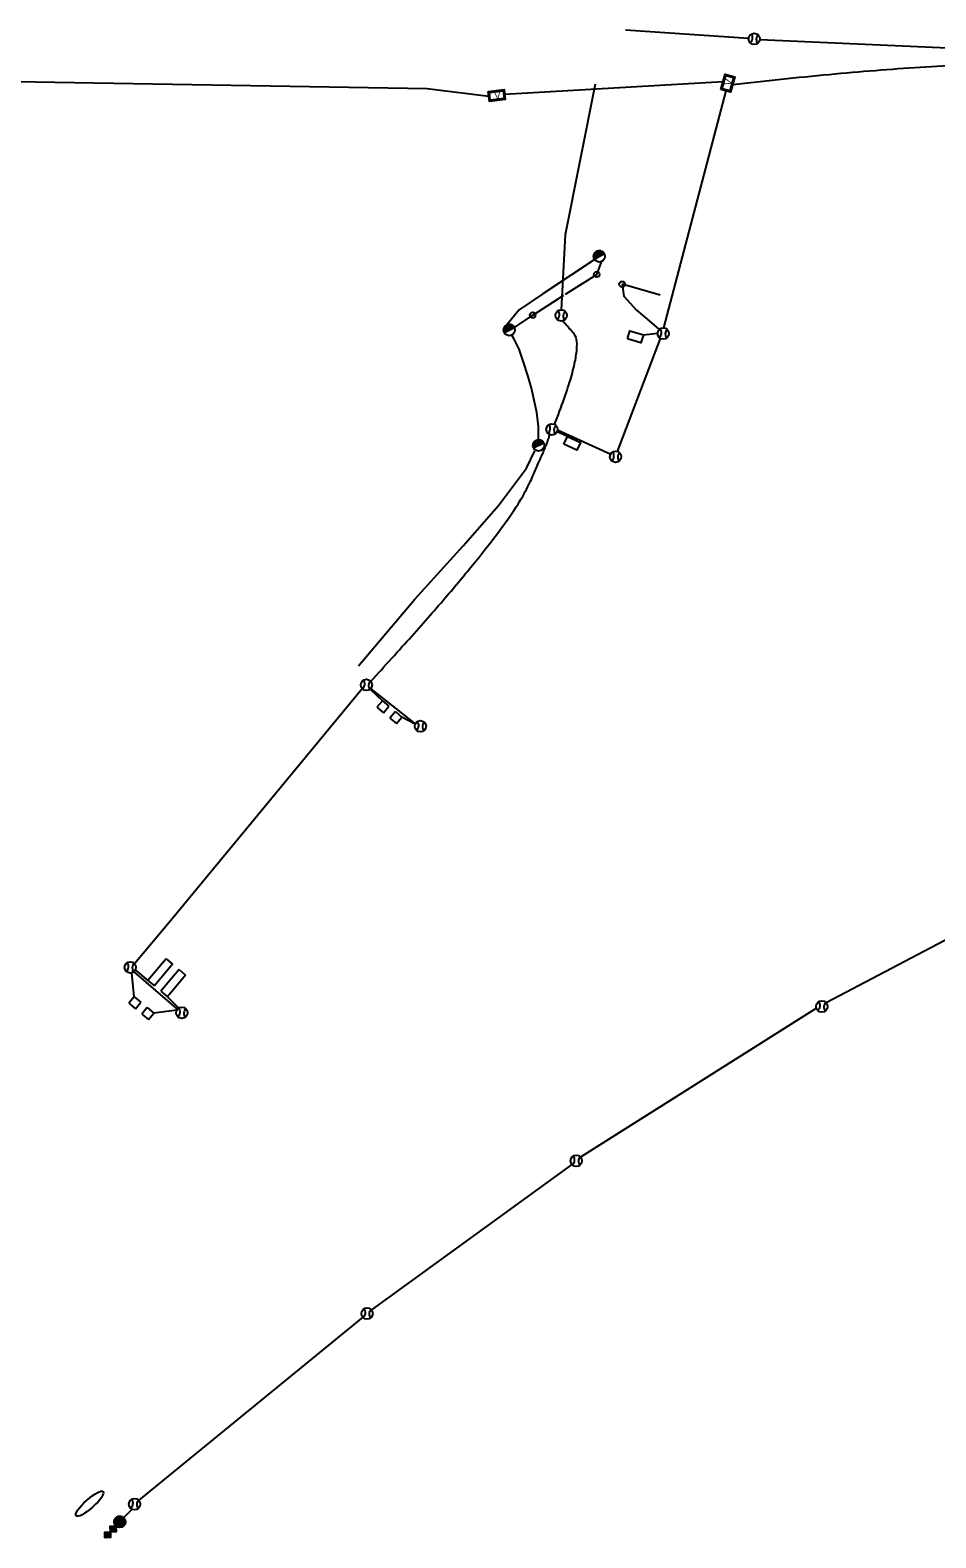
# Model space of a CAD drawing. Extents: x 0 to 2149228, y 0 to 2148913.
# Drawn here: x 595979 to 596619, y 230134 to 231199 of the extents above; entities that cross this region are included whole.
import ezdxf

# ---------------------------------------------------------------- set-up
doc = ezdxf.new("R2010")
doc.units = 0
for name, color, linetype in [('Default', 7, 'Continuous'), ('P_FTMS_2013 _CONDUIT', 7, 'Continuous'), ('P_FTMS_2013_NOT_CONDUIT', 7, 'Continuous'), ('P_TC_Drums_100_50', 7, 'Continuous')]:
    doc.layers.add(name, color=color, linetype=linetype)

# ---------------------------------------------------------------- blocks, each defined once
blk = doc.blocks.new('PB24X42')
at = {"layer": 'P_TC_Drums_100_50'}
blk.add_circle((0, 0), 2, dxfattribs=at)
for centre, start, end in [((-2.59, 0.09), 308.3742, 47.6044), ((2.73, 0.07), 134.4184, 228.4474)]:
    blk.add_arc(centre, 2, start, end, dxfattribs=at)

msp = doc.modelspace()

# ---------------------------------------------------------------- linework, layer by layer
at = {"layer": 'Default'}
for p, q in [((596378.3, 231041.9), (596377.2, 231038.6)), ((596377.8, 231041.3), (596377.2, 231039.3)), ((596378.6, 231042.2), (596377.3, 231038.1)), ((596381.1, 231039.1), (596377.3, 231040.4)), ((596379, 231042.5), (596377.4, 231037.7)), ((596381.4, 231039.3), (596377.4, 231040.6)), ((596379.3, 231042.6), (596377.5, 231037.4)), ((596381.8, 231039.4), (596377.5, 231040.8)), ((596382.1, 231039.6), (596377.6, 231041)), ((596377.6, 231037.3), (596384.7, 231040.9)), ((596379.6, 231042.8), (596377.8, 231037.4)), ((596382.4, 231039.7), (596377.8, 231041.2)), ((596382.7, 231039.9), (596377.9, 231041.5)), ((596379.9, 231042.9), (596378.1, 231037.6)), ((596383, 231040.1), (596378.1, 231041.7)), ((596383.3, 231040.2), (596378.2, 231041.9)), ((596380.1, 231043), (596378.4, 231037.7)), ((596383.6, 231040.4), (596378.4, 231042)), ((596383.9, 231040.5), (596378.6, 231042.2)), ((596380.4, 231043), (596378.7, 231037.9)), ((596384.2, 231040.7), (596378.9, 231042.4)), ((596380.7, 231043.1), (596379, 231038.1)), ((596384.5, 231040.8), (596379.1, 231042.6)), ((596380.9, 231043.1), (596379.3, 231038.2)), ((596384.7, 231041), (596379.4, 231042.7)), ((596381.2, 231043.1), (596379.6, 231038.4)), ((596384.5, 231041.3), (596379.8, 231042.9)), ((596381.4, 231043.1), (596379.9, 231038.5)), ((596384.2, 231041.7), (596380.1, 231043)), ((596381.7, 231043.1), (596380.2, 231038.7)), ((596381.9, 231043), (596380.5, 231038.8)), ((596383.9, 231042), (596380.6, 231043.1)), ((596382.2, 231043), (596380.8, 231039)), ((596382.4, 231042.9), (596381.1, 231039.1)), ((596383.4, 231042.4), (596381.3, 231043.1)), ((596382.6, 231042.8), (596381.4, 231039.3)), ((596382.8, 231042.8), (596381.8, 231039.4)), ((596383, 231042.6), (596382.1, 231039.6)), ((596383.3, 231042.5), (596382.4, 231039.7)), ((596383.5, 231042.4), (596382.7, 231039.9)), ((596383.7, 231042.2), (596383, 231040.1)), ((596383.9, 231042.1), (596383.3, 231040.2)), ((596384.1, 231041.9), (596383.6, 231040.4)), ((596384.2, 231041.7), (596383.9, 231040.5)), ((596384.4, 231041.4), (596384.2, 231040.7)), ((596384.6, 231041.2), (596384.5, 231040.8)), ((596384.7, 231041), (596384.7, 231040.9)), ((596380.5, 231038.8), (596377.2, 231039.9)), ((596380.2, 231038.7), (596377.2, 231039.7)), ((596379.9, 231038.5), (596377.2, 231039.4)), ((596379.6, 231038.4), (596377.2, 231039.2)), ((596379.3, 231038.2), (596377.2, 231038.9)), ((596379, 231038.1), (596377.2, 231038.7)), ((596378.7, 231037.9), (596377.2, 231038.4)), ((596380.8, 231039), (596377.3, 231040.1)), ((596378.4, 231037.7), (596377.3, 231038.1)), ((596378.1, 231037.6), (596377.4, 231037.8)), ((596377.8, 231037.4), (596377.5, 231037.6)), ((596377.6, 231037.3), (596377.6, 231037.3)), ((596377.6, 231037.3), (596377.6, 231037.3)), ((596379.3, 231026.4), (596383, 231035.6)), ((596357.4, 231012.4), (596379.3, 231026.4)), ((596424.1, 231011.6), (596397.2, 231019.4)), ((596334.1, 230997.6), (596356.1, 231011.6)), ((596316.1, 230986.3), (596313.6, 230987.2)), ((596314.7, 230989.9), (596313.7, 230986.6)), ((596314.3, 230989.3), (596313.7, 230987.3)), ((596317, 230986.8), (596313.7, 230987.9)), ((596316.7, 230986.7), (596313.7, 230987.6)), ((596316.4, 230986.5), (596313.7, 230987.4)), ((596315.1, 230990.2), (596313.8, 230986.1)), ((596317.6, 230987.1), (596313.8, 230988.4)), ((596317.3, 230987), (596313.8, 230988.1)), ((596315.4, 230990.5), (596313.9, 230985.7)), ((596317.9, 230987.3), (596313.9, 230988.6)), ((596315.7, 230990.6), (596314, 230985.4)), ((596318.2, 230987.4), (596314, 230988.8)), ((596318.5, 230987.6), (596314.1, 230989)), ((596314.1, 230985.3), (596321.2, 230988.9)), ((596316.1, 230990.8), (596314.3, 230985.4)), ((596318.8, 230987.7), (596314.3, 230989.2)), ((596319.1, 230987.9), (596314.4, 230989.4)), ((596319.4, 230988), (596314.5, 230989.6)), ((596316.3, 230990.9), (596314.6, 230985.6)), ((596319.8, 230988.2), (596314.7, 230989.8)), ((596316.6, 230991), (596314.9, 230985.7)), ((596320.1, 230988.3), (596314.9, 230990)), ((596320.4, 230988.5), (596315.1, 230990.2)), ((596316.9, 230991), (596315.2, 230985.9)), ((596320.7, 230988.7), (596315.3, 230990.4)), ((596317.2, 230991.1), (596315.5, 230986)), ((596321, 230988.8), (596315.6, 230990.5)), ((596317.4, 230991.1), (596315.8, 230986.2)), ((596321.2, 230989), (596315.9, 230990.7)), ((596317.7, 230991.1), (596316.1, 230986.3)), ((596321, 230989.3), (596316.2, 230990.8)), ((596317.9, 230991.1), (596316.4, 230986.5)), ((596320.7, 230989.6), (596316.6, 230991)), ((596318.2, 230991.1), (596316.7, 230986.7)), ((596318.4, 230991), (596317, 230986.8)), ((596320.4, 230990), (596317.1, 230991.1)), ((596318.6, 230991), (596317.3, 230987)), ((596318.9, 230990.9), (596317.6, 230987.1)), ((596319.9, 230990.4), (596317.8, 230991.1)), ((596319.1, 230990.8), (596317.9, 230987.3)), ((596319.3, 230990.7), (596318.2, 230987.4)), ((596319.5, 230990.6), (596318.5, 230987.6)), ((596319.7, 230990.5), (596318.8, 230987.7)), ((596320, 230990.4), (596319.1, 230987.9)), ((596320.2, 230990.2), (596319.4, 230988)), ((596320.4, 230990), (596319.8, 230988.2)), ((596320.5, 230989.8), (596320.1, 230988.3)), ((596320.7, 230989.6), (596320.4, 230988.5)), ((596320.9, 230989.4), (596320.7, 230988.7)), ((596321.1, 230989.1), (596321, 230988.8)), ((596321.2, 230988.9), (596334.1, 230997.6)), ((596321.2, 230989), (596321.2, 230988.9)), ((596315.8, 230986.2), (596313.6, 230986.9)), ((596315.5, 230986), (596313.7, 230986.6)), ((596315.2, 230985.9), (596313.7, 230986.4)), ((596314.9, 230985.7), (596313.8, 230986.1)), ((596314.6, 230985.6), (596313.9, 230985.8)), ((596314.3, 230985.4), (596314, 230985.5)), ((596314.1, 230985.3), (596314.1, 230985.3)), ((596314.1, 230985.3), (596314.1, 230985.3)), ((596335, 230907.8), (596334.3, 230905.8)), ((596337.1, 230905), (596334.3, 230905.9)), ((596336.8, 230904.8), (596334.3, 230905.6)), ((596336.5, 230904.7), (596334.3, 230905.4)), ((596335.4, 230908.3), (596334.4, 230905.1)), ((596337.7, 230905.3), (596334.4, 230906.4)), ((596337.4, 230905.1), (596334.4, 230906.1)), ((596336.2, 230904.5), (596334.4, 230905.1)), ((596335.9, 230904.4), (596334.4, 230904.8)), ((596335.8, 230908.7), (596334.5, 230904.6)), ((596338.3, 230905.6), (596334.5, 230906.8)), ((596338, 230905.4), (596334.5, 230906.6)), ((596335.6, 230904.2), (596334.5, 230904.6)), ((596336.1, 230908.9), (596334.6, 230904.2)), ((596338.6, 230905.7), (596334.6, 230907)), ((596335.3, 230904), (596334.6, 230904.3)), ((596336.4, 230909.1), (596334.7, 230903.8)), ((596338.9, 230905.9), (596334.7, 230907.3)), ((596335, 230903.9), (596334.7, 230904)), ((596339.2, 230906), (596334.8, 230907.5)), ((596334.8, 230903.8), (596341.9, 230907.4)), ((596334.8, 230903.8), (596334.8, 230903.8)), ((596334.8, 230903.8), (596334.8, 230903.8)), ((596339.5, 230906.2), (596334.9, 230907.7)), ((596336.7, 230909.2), (596335, 230903.9)), ((596339.8, 230906.4), (596335.1, 230907.9)), ((596340.1, 230906.5), (596335.2, 230908.1)), ((596337, 230909.4), (596335.3, 230904)), ((596340.4, 230906.7), (596335.4, 230908.3)), ((596337.3, 230909.5), (596335.6, 230904.2)), ((596340.7, 230906.8), (596335.6, 230908.5)), ((596341, 230907), (596335.8, 230908.7)), ((596337.6, 230909.5), (596335.9, 230904.4)), ((596341.4, 230907.1), (596336, 230908.9)), ((596337.8, 230909.5), (596336.2, 230904.5)), ((596341.7, 230907.3), (596336.3, 230909)), ((596338.1, 230909.6), (596336.5, 230904.7)), ((596341.8, 230907.5), (596336.6, 230909.2)), ((596338.4, 230909.6), (596336.8, 230904.8)), ((596341.7, 230907.8), (596336.9, 230909.3)), ((596338.6, 230909.6), (596337.1, 230905)), ((596341.4, 230908.1), (596337.3, 230909.4)), ((596338.9, 230909.5), (596337.4, 230905.1)), ((596339.1, 230909.5), (596337.7, 230905.3)), ((596341.1, 230908.5), (596337.8, 230909.5)), ((596339.3, 230909.5), (596338, 230905.4)), ((596339.6, 230909.4), (596338.3, 230905.6)), ((596340.6, 230908.9), (596338.5, 230909.6)), ((596339.8, 230909.3), (596338.6, 230905.7)), ((596340, 230909.2), (596338.9, 230905.9)), ((596340.2, 230909.1), (596339.2, 230906)), ((596340.4, 230909), (596339.5, 230906.2)), ((596340.6, 230908.8), (596339.8, 230906.4)), ((596340.8, 230908.7), (596340.1, 230906.5)), ((596341, 230908.5), (596340.4, 230906.7)), ((596341.2, 230908.3), (596340.7, 230906.8)), ((596341.4, 230908.1), (596341, 230907)), ((596341.6, 230907.9), (596341.4, 230907.1)), ((596341.8, 230907.6), (596341.7, 230907.3)), ((596341.9, 230907.4), (596341.9, 230907.4))]:
    msp.add_line(p, q, dxfattribs=at)
for points in [[(596381.1, 231039.1), (596341.2, 231012.7), (596324.5, 231001.4), (596315.8, 230990.7)], [(596397.2, 231019.4), (596398.4, 231010.9), (596407.4, 231001.1), (596416.3, 230993.5), (596425, 230986.1)], [(596338.3, 230905.6), (596338.3, 230919), (596337, 230928.9), (596333.2, 230946.1), (596330.9, 230954.2), (596327.1, 230965.8), (596324.5, 230973.6), (596321, 230980.6), (596319.4, 230983.5)], [(596211.2, 230750), (596250.9, 230797), (596285, 230834.7), (596310, 230863.3), (596329.7, 230889.6), (596335.6, 230901.9)]]:
    msp.add_lwpolyline(points, dxfattribs=at)
for centre, radius in [((596381.1, 231039.1), 4), ((596379.3, 231026.4), 2), ((596397.2, 231019.4), 2), ((596334.1, 230997.6), 2), ((596317.6, 230987.1), 4), ((596338.3, 230905.6), 4)]:
    msp.add_circle(centre, radius, dxfattribs=at)
for centre in [(596381.1, 231039.1), (596317.6, 230987.1), (596338.3, 230905.6)]:
    msp.add_arc(centre, 4, 26.9489, 206.9489, dxfattribs=at)
at = {"layer": 'P_FTMS_2013 _CONDUIT'}
for p, q in [((596486.6, 231192.9), (596399.6, 231198.8)), ((596494.6, 231192.3), (596754.6, 231180.7)), ((596259.5, 231157.4), (595848.1, 231164.4)), ((596468.6, 231162.3), (596314.3, 231153.4)), ((596303.1, 231152), (596259.5, 231157.4)), ((596470.5, 231156), (596426.6, 230988.6)), ((596394, 230901.4), (596424.4, 230981)), ((596351.7, 230916.6), (596389.2, 230899.4)), ((596078.5, 230570.5), (596213.7, 230734)), ((596219.8, 230733.8), (596251.2, 230709.1)), ((596709.9, 230600.7), (596541.4, 230512.1)), ((596052.8, 230539.8), (596078.5, 230570.5)), ((596052.5, 230534), (596083, 230507.6)), ((596534.5, 230508.3), (596367.9, 230403.1)), ((596361.8, 230397.9), (596220.2, 230295.3)), ((596214.1, 230290.1), (596055.9, 230160.9)), ((596051.2, 230154.6), (596045.2, 230148.5))]:
    msp.add_line(p, q, dxfattribs=at)
msp.add_lwpolyline([(596354.5, 231001.3), (596357.2, 231054.5), (596378.5, 231160.8)], dxfattribs=at)
for points in [[(596475.4, 231160.5), (596683.6, 231184.5), (596974.5, 231163.5), (597098.7, 231160.7), (597098.7, 231160.7), (597098.7, 231160.7)], [(596349.6, 230920.5), (596371.2, 230975.3), (596355.4, 230993.5), (596355.4, 230993.5)], [(596219.8, 230739.1), (596315.8, 230843.6), (596347.4, 230913), (596345.9, 230913.4)]]:
    msp.add_open_spline(points, degree=2, dxfattribs=at)
at = {"layer": 'P_FTMS_2013_NOT_CONDUIT'}
for p, q in [((596412.3, 230983.8), (596422.3, 230984.9)), ((596358.7, 230911.9), (596351.4, 230915.3)), ((596219.3, 230733.5), (596228, 230725.4)), ((596228, 230725.4), (596224.1, 230720.8)), ((596228, 230725.4), (596232.6, 230721.5)), ((596228.7, 230716.9), (596232.6, 230721.5)), ((596224.1, 230720.8), (596228.7, 230716.9)), ((596237.2, 230717.7), (596233.3, 230713.1)), ((596233.3, 230713.1), (596237.9, 230709.2)), ((596237.2, 230717.7), (596241.8, 230713.8)), ((596237.9, 230709.2), (596241.8, 230713.8)), ((596251, 230708.7), (596241.8, 230713.8)), ((596075.2, 230543.2), (596062.4, 230527.9)), ((596075.2, 230543.2), (596079.8, 230539.4)), ((596052.7, 230516.4), (596051.1, 230533.2)), ((596053.5, 230535.2), (596062.4, 230527.9)), ((596079.8, 230539.4), (596067, 230524)), ((596084.4, 230535.5), (596071.6, 230520.2)), ((596089, 230531.6), (596076.2, 230516.3)), ((596084.4, 230535.5), (596089, 230531.6)), ((596062.4, 230527.9), (596067, 230524)), ((596071.6, 230520.2), (596076.2, 230516.3)), ((596052.7, 230516.4), (596048.9, 230511.8)), ((596048.9, 230511.8), (596053.5, 230507.9)), ((596052.7, 230516.4), (596057.3, 230512.5)), ((596053.5, 230507.9), (596057.3, 230512.5)), ((596061.9, 230508.7), (596058.1, 230504.1)), ((596061.9, 230508.7), (596066.5, 230504.8)), ((596076.2, 230516.3), (596084.1, 230508.4)), ((596058.1, 230504.1), (596062.7, 230500.2)), ((596062.7, 230500.2), (596066.5, 230504.8)), ((596082.7, 230507), (596066.5, 230504.8)), ((596046.4, 230146.5), (596038.5, 230146.2)), ((596046.4, 230146.2), (596038.5, 230146)), ((596046.3, 230146.9), (596038.6, 230146.7)), ((596046.3, 230146.7), (596038.6, 230146.4)), ((596038.7, 230144.4), (596038.6, 230146.6)), ((596046.1, 230147.2), (596038.7, 230146.9)), ((596046, 230147.4), (596038.8, 230147.2)), ((596038.9, 230143.8), (596038.8, 230147.2)), ((596045.9, 230147.6), (596038.9, 230147.4)), ((596045.8, 230147.9), (596039.1, 230147.7)), ((596039.2, 230143.3), (596039.1, 230147.6)), ((596045.6, 230148.1), (596039.2, 230147.9)), ((596039.4, 230143), (596039.3, 230148)), ((596045.4, 230148.3), (596039.4, 230148.2)), ((596039.7, 230142.8), (596039.5, 230148.3)), ((596045.2, 230148.6), (596039.6, 230148.4)), ((596039.9, 230142.5), (596039.7, 230148.5)), ((596044.9, 230148.8), (596039.9, 230148.6)), ((596040.2, 230142.3), (596040, 230148.7)), ((596044.5, 230149), (596040.2, 230148.9)), ((596040.4, 230142.2), (596040.2, 230148.9)), ((596040.7, 230142), (596040.4, 230149)), ((596044.1, 230149.3), (596040.6, 230149.2)), ((596040.9, 230141.9), (596040.7, 230149.2)), ((596041.2, 230141.8), (596040.9, 230149.3)), ((596043.4, 230149.5), (596041.2, 230149.4)), ((596041.4, 230141.8), (596041.2, 230149.4)), ((596041.6, 230141.7), (596041.4, 230149.5)), ((596041.9, 230141.7), (596041.6, 230149.5)), ((596042.1, 230141.6), (596041.9, 230149.6)), ((596042.4, 230141.6), (596042.1, 230149.6)), ((596042.6, 230141.6), (596042.3, 230149.6)), ((596042.8, 230141.6), (596042.6, 230149.6)), ((596043.1, 230141.7), (596042.8, 230149.6)), ((596043.3, 230141.7), (596043.1, 230149.6)), ((596043.6, 230141.8), (596043.3, 230149.5)), ((596043.8, 230141.8), (596043.6, 230149.4)), ((596044, 230141.9), (596043.8, 230149.4)), ((596044.3, 230142.1), (596044, 230149.3)), ((596044.5, 230142.2), (596044.3, 230149.2)), ((596044.7, 230142.3), (596044.5, 230149)), ((596045, 230142.5), (596044.8, 230148.9)), ((596045.2, 230142.7), (596045, 230148.7)), ((596045.4, 230142.9), (596045.3, 230148.5)), ((596045.7, 230143.2), (596045.5, 230148.2)), ((596045.9, 230143.6), (596045.8, 230147.9)), ((596046.1, 230144), (596046, 230147.4)), ((596046.4, 230144.7), (596046.3, 230146.8)), ((596033.7, 230138.4), (596031.9, 230136.5)), ((596033.4, 230138.4), (596031.9, 230136.8)), ((596033.1, 230138.4), (596031.9, 230137.1)), ((596034.8, 230138.4), (596031.9, 230135.4)), ((596032.7, 230138.4), (596031.9, 230137.5)), ((596034.4, 230138.4), (596031.9, 230135.8)), ((596032.4, 230138.4), (596031.9, 230137.8)), ((596034.1, 230138.4), (596031.9, 230136.1)), ((596036, 230134.5), (596031.9, 230138.3)), ((596032, 230138.3), (596031.9, 230138.1)), ((596035.6, 230134.5), (596031.9, 230138)), ((596035.3, 230134.5), (596031.9, 230137.7)), ((596035, 230134.4), (596031.9, 230137.3)), ((596034.6, 230134.4), (596031.9, 230137)), ((596034.3, 230134.4), (596031.9, 230136.6)), ((596033.9, 230134.4), (596031.9, 230136.3)), ((596033.6, 230134.4), (596031.9, 230136)), ((596033.3, 230134.4), (596031.9, 230135.6)), ((596035.8, 230138.5), (596032, 230134.4)), ((596035.4, 230138.5), (596032, 230134.8)), ((596035.1, 230138.4), (596032, 230135.1)), ((596036, 230134.8), (596032.2, 230138.4)), ((596035.9, 230138.2), (596032.3, 230134.4)), ((596036, 230135.2), (596032.5, 230138.4)), ((596035.9, 230137.9), (596032.6, 230134.4)), ((596035.9, 230135.5), (596032.9, 230138.4)), ((596035.9, 230137.5), (596032.9, 230134.4)), ((596035.9, 230135.8), (596033.2, 230138.4)), ((596035.9, 230137.2), (596033.3, 230134.4)), ((596035.9, 230136.2), (596033.6, 230138.4)), ((596035.9, 230136.8), (596033.6, 230134.4)), ((596035.9, 230136.5), (596033.9, 230138.4)), ((596035.9, 230136.5), (596033.9, 230134.4)), ((596035.9, 230136.8), (596034.2, 230138.4)), ((596035.9, 230136.2), (596034.3, 230134.4)), ((596035.9, 230137.2), (596034.6, 230138.4)), ((596035.9, 230135.8), (596034.6, 230134.4)), ((596035.9, 230137.5), (596034.9, 230138.4)), ((596035.9, 230137.9), (596035.2, 230138.5)), ((596035.9, 230138.2), (596035.6, 230138.5)), ((596039.9, 230138.6), (596035.7, 230142.5)), ((596036.3, 230142.5), (596035.7, 230141.9)), ((596035.9, 230142.5), (596035.7, 230142.3)), ((596039.5, 230138.6), (596035.7, 230142.1)), ((596039.2, 230138.6), (596035.7, 230141.8)), ((596039.6, 230142.6), (596035.8, 230138.5)), ((596039.3, 230142.6), (596035.8, 230138.9)), ((596039, 230142.6), (596035.8, 230139.2)), ((596038.6, 230142.6), (596035.8, 230139.6)), ((596038.3, 230142.6), (596035.8, 230139.9)), ((596037.6, 230142.5), (596035.8, 230140.6)), ((596037.3, 230142.5), (596035.8, 230140.9)), ((596036.9, 230142.5), (596035.8, 230141.3)), ((596036.6, 230142.5), (596035.8, 230141.6)), ((596038, 230142.5), (596035.8, 230140.2)), ((596038.8, 230138.6), (596035.8, 230141.5)), ((596038.5, 230138.6), (596035.8, 230141.1)), ((596038.2, 230138.5), (596035.8, 230140.8)), ((596037.8, 230138.5), (596035.8, 230140.4)), ((596037.5, 230138.5), (596035.8, 230140.1)), ((596037.1, 230138.5), (596035.8, 230139.8)), ((596036.8, 230138.5), (596035.8, 230139.4)), ((596036.5, 230138.5), (596035.8, 230139.1)), ((596036.1, 230138.5), (596035.8, 230138.7)), ((596039.8, 230138.9), (596036.1, 230142.5)), ((596039.7, 230142.3), (596036.1, 230138.5)), ((596039.8, 230139.3), (596036.4, 230142.5)), ((596039.7, 230142), (596036.5, 230138.5)), ((596039.8, 230139.6), (596036.7, 230142.5)), ((596039.8, 230141.7), (596036.8, 230138.5)), ((596039.8, 230140), (596037.1, 230142.5)), ((596039.8, 230141.3), (596037.1, 230138.5)), ((596039.8, 230140.3), (596037.4, 230142.5)), ((596039.8, 230141), (596037.5, 230138.5)), ((596039.8, 230140.6), (596037.8, 230142.5)), ((596039.8, 230140.6), (596037.8, 230138.5)), ((596039.8, 230141), (596038.1, 230142.5)), ((596039.8, 230140.3), (596038.2, 230138.5)), ((596039.8, 230141.3), (596038.4, 230142.6)), ((596046.4, 230146), (596038.5, 230145.7)), ((596046.5, 230145.7), (596038.5, 230145.5)), ((596046.5, 230145.5), (596038.5, 230145.2)), ((596046.4, 230145.3), (596038.5, 230145)), ((596039.8, 230140), (596038.5, 230138.6)), ((596046.4, 230145), (596038.6, 230144.8)), ((596046.4, 230144.8), (596038.6, 230144.5)), ((596046.3, 230144.5), (596038.7, 230144.3)), ((596046.3, 230144.3), (596038.8, 230144.1)), ((596039.8, 230141.7), (596038.8, 230142.6)), ((596039.8, 230139.6), (596038.8, 230138.6)), ((596046.1, 230144), (596038.9, 230143.8)), ((596046, 230143.8), (596039, 230143.6)), ((596039.7, 230142), (596039.1, 230142.6)), ((596045.9, 230143.6), (596039.2, 230143.3)), ((596039.8, 230139.3), (596039.2, 230138.6)), ((596045.7, 230143.3), (596039.4, 230143.1)), ((596039.7, 230142.3), (596039.5, 230142.6)), ((596039.8, 230138.9), (596039.5, 230138.6)), ((596045.6, 230143.1), (596039.6, 230142.9)), ((596045.3, 230142.8), (596039.8, 230142.6)), ((596045.1, 230142.6), (596040.1, 230142.4)), ((596044.7, 230142.3), (596040.4, 230142.2)), ((596044.3, 230142.1), (596040.9, 230142)), ((596043.7, 230141.8), (596041.5, 230141.7)), ((596032.9, 230134.4), (596032, 230135.3)), ((596032.6, 230134.4), (596032, 230134.9)), ((596032.3, 230134.4), (596032, 230134.6)), ((596035.9, 230135.5), (596035, 230134.4)), ((596036, 230135.2), (596035.3, 230134.5)), ((596036, 230134.8), (596035.6, 230134.5))]:
    msp.add_line(p, q, dxfattribs=at)
for points in [[(596467.1, 231156.9), (596470.1, 231167.8), (596476.9, 231165.9), (596473.9, 231155)], [(596467.4, 231157.1), (596470.3, 231167.5), (596476.6, 231165.7), (596473.7, 231155.3)], [(596467.7, 231157.2), (596470.5, 231167.2), (596476.3, 231165.6), (596473.6, 231155.6)], [(596468, 231157.4), (596470.6, 231166.9), (596476, 231165.4), (596473.4, 231155.9)], [(596302.6, 231155.5), (596313.9, 231156.9), (596314.7, 231149.9), (596303.5, 231148.5)], [(596302.9, 231155.3), (596313.6, 231156.6), (596314.4, 231150.1), (596303.7, 231148.8)], [(596303.2, 231155.1), (596313.4, 231156.3), (596314.2, 231150.3), (596303.9, 231149.1)], [(596303.5, 231154.8), (596313.2, 231156), (596313.9, 231150.5), (596304.1, 231149.3)], [(596401, 230980.8), (596402.7, 230986.6), (596412.3, 230983.8), (596410.6, 230978.1)], [(596356.2, 230906.5), (596358.7, 230911.9), (596367.8, 230907.7), (596365.3, 230902.3)], [(596032, 230134.3), (596031.9, 230138.3), (596035.9, 230138.5), (596036, 230134.5)], [(596035.9, 230138.5), (596035.7, 230142.5), (596039.7, 230142.6), (596039.9, 230138.6)]]:
    msp.add_lwpolyline(points, close=True, dxfattribs=at)
msp.add_circle((596042.5, 230145.6), 4, dxfattribs=at)
msp.add_ellipse((596021.2, 230158.4), major_axis=(-9.57, -8.53), ratio=0.249166, dxfattribs=at)

# ---------------------------------------------------------------- block references
at = {"layer": 'P_FTMS_2013_NOT_CONDUIT', "xscale": 2, "yscale": 2.0000000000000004, "rotation": -4.918194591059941}
for p in [(596490.6, 231192.6), (596354.2, 230997.4), (596426.3, 230984.6), (596347.7, 230916.9), (596392.7, 230897.6), (596216.7, 230736.5), (596254.8, 230707.3), (596049.9, 230537.1), (596086.3, 230505.1), (596538.3, 230509.5), (596364.9, 230400.5), (596217.1, 230292.7), (596053, 230158.1)]:
    msp.add_blockref('PB24X42', p, dxfattribs=at)

# ---------------------------------------------------------------- texts
at = {"layer": 'P_FTMS_2013_NOT_CONDUIT'}
for rotation, p in [(74.5424, (596474, 231159.2)), (6.9112, (596307.4, 231150))]:
    msp.add_text('V', height=4.96, rotation=rotation, dxfattribs=at).set_placement(p)

doc.saveas('drawing.dxf')
